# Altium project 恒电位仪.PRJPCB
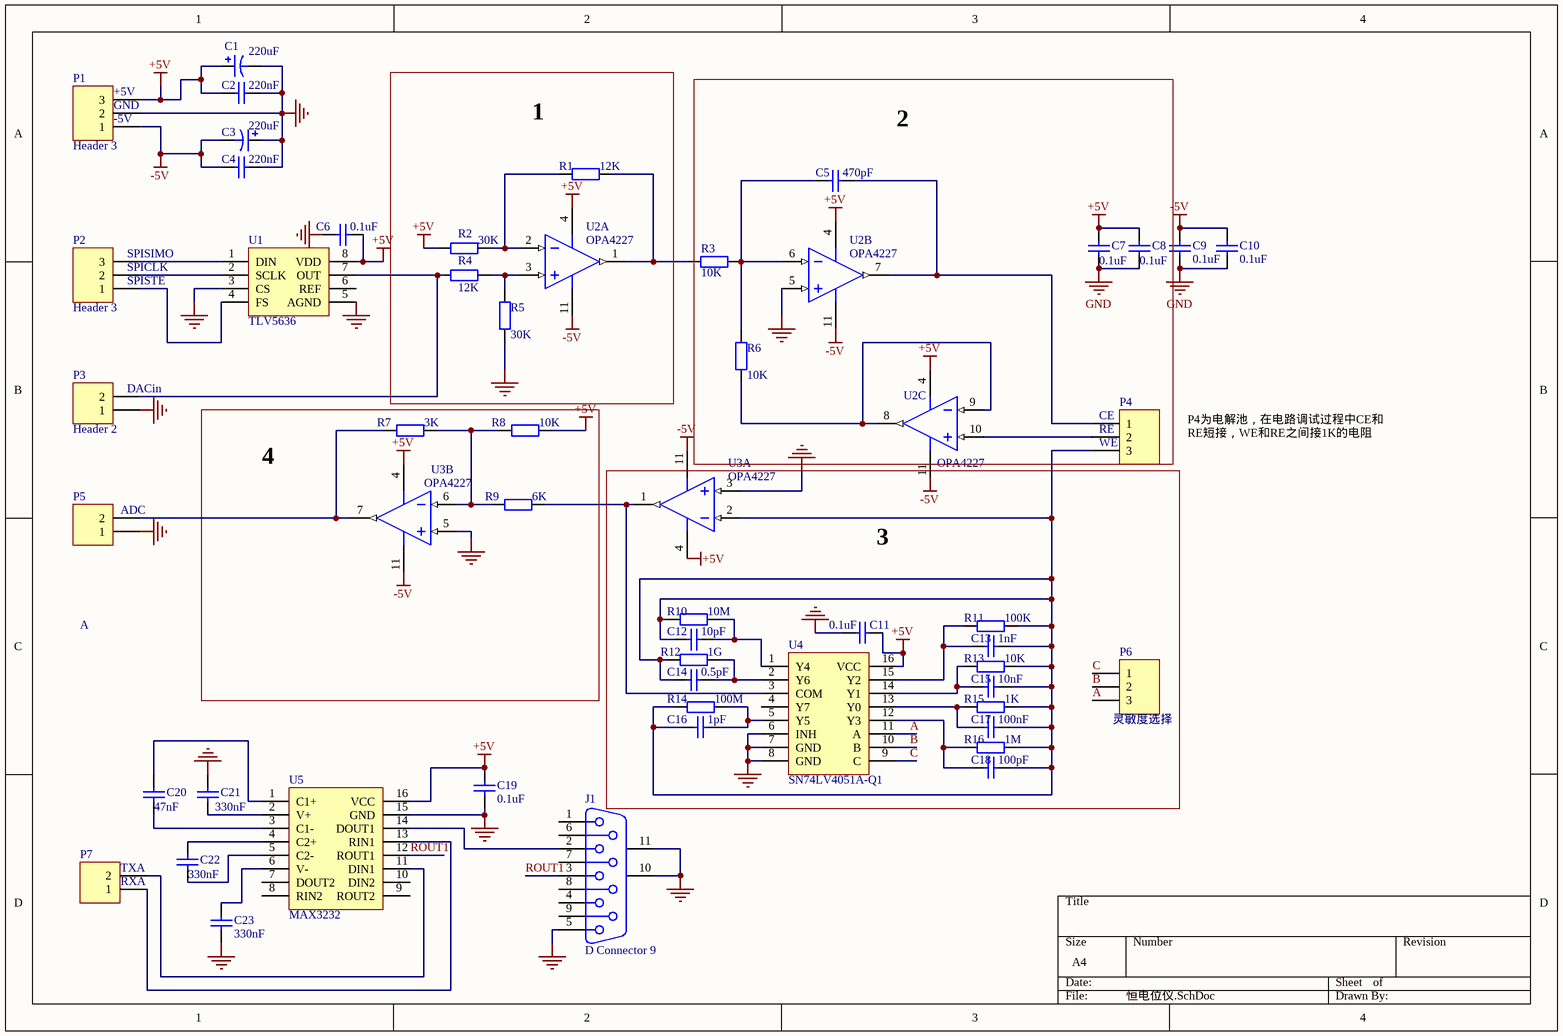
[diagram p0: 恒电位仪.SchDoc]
1 sheet, 52 parts. Net scope: global (net labels, ports and power ports of the same name join across sheets).
Board file: 恒电位仪.PcbDoc

## Sheet 恒电位仪.SchDoc
size A4

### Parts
C1  value 220uF  [R38]  (hidden comment: Cap Pol1)
C2  value 220nF  [CAPR5-4X5]  (hidden comment: Cap)
C3  value 220uF  [R38]  (hidden comment: Cap Pol1)
C4  value 220nF  [CAPR5-4X5]  (hidden comment: Cap)
C5  value 470pF  [C0805]  (hidden comment: Cap)
C6  value 0.1uF  [C0805]  (hidden comment: Cap)
C7  value 0.1uF  [C0805]  (hidden comment: Cap)
C8  value 0.1uF  [C0805]  (hidden comment: Cap)
C9  value 0.1uF  [C0805]  (hidden comment: Cap)
C10  value 0.1uF  [C0805]  (hidden comment: Cap)
C11  value 0.1uF  [C0805]  (hidden comment: Cap)
C12  value 10pF  [C0805]  (hidden comment: Cap)
C13  value 1nF  [C0805]  (hidden comment: Cap)
C14  value 0.5pF  [C0805]  (hidden comment: Cap)
C15  value 10nF  [C0805]  (hidden comment: Cap)
C16  value 1pF  [C0805]  (hidden comment: Cap)
C17  value 100nF  [C0805]  (hidden comment: Cap)
C18  value 100pF  [C0805]  (hidden comment: Cap)
C19  value 0.1uF  [C0805]  (hidden comment: Cap)
C20  value 47nF  [C0805]  (hidden comment: Cap)
C21  value 330nF  [C0805]  (hidden comment: Cap)
C22  value 330nF  [C0805]  (hidden comment: Cap)
C23  value 330nF  [C0805]  (hidden comment: Cap)
J1  D Connector 9  [DSUB1.385-2H9]
P1  Header 3  [HDR1X3]
P2  Header 3  [HDR1X3]
P3  Header 2  [HDR1X2]
P4  Header 3  [HDR1X3]  (value not drawn)
P5  Header 2  [HDR1X2]  (value not drawn)
P6  Header 3  [HDR1X3]  (value not drawn)
P7  Header 2  [HDR1X2]  (value not drawn)
R1  value 12K  [6-0805]  (hidden comment: Res2)
R2  value 30K  [6-0805]  (hidden comment: Res2)
R3  value 10K  [6-0805]  (hidden comment: Res2)
R4  value 12K  [6-0805]  (hidden comment: Res2)
R5  value 30K  [6-0805]  (hidden comment: Res2)
R6  value 10K  [6-0805]  (hidden comment: Res2)
R7  value 3K  [6-0805]  (hidden comment: Res2)
R8  value 10K  [6-0805]  (hidden comment: Res2)
R9  value 6K  [6-0805]  (hidden comment: Res2)
R10  value 10M  [AXIAL-0.4]  (hidden comment: Res2)
R11  value 100K  [AXIAL-0.4]  (hidden comment: Res2)
R12  value 1G  [AXIAL-0.4]  (hidden comment: Res2)
R13  value 10K  [AXIAL-0.4]  (hidden comment: Res2)
R14  value 100M  [AXIAL-0.4]  (hidden comment: Res2)
R15  value 1K  [AXIAL-0.4]  (hidden comment: Res2)
R16  value 1M  [AXIAL-0.4]  (hidden comment: Res2)
U1  TLV5636  [TLV5636]
U2  OPA4227  [OPA4227]  (parts A,B,C of 4)
U3  OPA4227  [OPA4227]  (parts A,B of 4)
U4  SN74LV4051A-Q1  [SN74LV4051A-Q1]
U5  MAX3232  [MAX3232]

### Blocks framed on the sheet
1: R1 R2 R4 R5 U2
2: C5 C7 C8 P4 R3 R6 U2
4: R7-R9 U3
3: C11-C18 P6 R10-R16 U3 U4

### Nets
+5V: C1.1 C2.1 C6.1 C7.1 C8.1 C11.2 C19.1 P1.3 R2.1 R8.1 U1.8(VDD) U2.4(V+) U3.4(V+) U4.16(VCC) U5.16(VCC)
-5V: C3.2 C4.1 C9.1 C10.1 P1.1 U2.11(V-) U3.11(V-)
GND: C1.2 C2.2 C3.1 C4.2 C6.2 C7.2 C8.2 C9.2 C10.2 C11.1 C19.2 C21.1 C23.2 J1.5 J1.10(MH1) J1.11(MH2) P1.2 P3.1 P5.1 R5.1 U1.3(CS) U1.5(AGND) U2.5(IN+) U3.3(IN+) U3.5(IN+) U4.6(INH) U4.7(GND) U4.8(GND) U5.15(GND)
A: P6.3 U4.11(A)
B: P6.2 U4.10(B)
C: P6.1 U4.9(C)
ROUT1: J1.3 U5.12(ROUT1)
NetC5_1: C5.1 P4.1 U2.7(OUT)
NetC5_2: C5.2 R3.1 R6.2 U2.6(IN-)
NetC12_1: C12.1 R10.1 U4.1(Y4)
NetC12_2: C12.2 C13.1 C14.2 C15.1 C16.2 C17.1 C18.1 P4.3 R10.2 R11.1 R12.2 R13.1 R14.2 R15.1 R16.1 U3.2(IN-)
NetC13_2: C13.2 R11.2 U4.15(Y2)
NetC14_1: C14.1 R12.1 U4.2(Y6)
NetC15_2: C15.2 R13.2 U4.14(Y1)
NetC16_1: C16.1 R14.1 U4.5(Y5)
NetC17_2: C17.2 R15.2 U4.13(Y0)
NetC18_2: C18.2 R16.2 U4.12(Y3)
NetC20_1: C20.1 U5.1(C1+)
NetC20_2: C20.2 U5.3(C1-)
NetC21_2: C21.2 U5.2(V+)
NetC22_1: C22.1 U5.4(C2+)
NetC22_2: C22.2 U5.5(C2-)
NetC23_1: C23.1 U5.6(V-)
NetJ1_2: J1.2 U5.14(DOUT1)
NetP2_1: P2.1 U1.4(FS)
NetP2_2: P2.2 U1.2(SCLK)
NetP2_3: P2.3 U1.1(DIN)
NetP3_2: P3.2 R4.1 U1.7(OUT)
NetP4_2: P4.2 U2.10(IN+)
NetP5_2: P5.2 R7.2 U3.7(OUT)
NetP7_1: P7.1 U5.13(RIN1)
NetP7_2: P7.2 U5.11(DIN1)
NetR1_1: R1.1 R2.2 U2.2(IN-)
NetR1_2: R1.2 R3.2 U2.1(OUT)
NetR4_2: R4.2 R5.2 U2.3(IN+)
NetR6_1: R6.1 U2.8(OUT) U2.9(IN-)
NetR7_1: R7.1 R8.2 R9.2 U3.6(IN-)
NetR9_1: R9.1 U3.1(OUT) U4.3(COM)

Not connected (* = marked no-connect by the designer): J1 1 4 6 7 8 9; U1 6(REF); U4 4(Y7); U5 7(DOUT2) 8(RIN2) 9(ROUT2) 10(DIN2)

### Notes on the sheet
- (near P1) +5V
- (near P1) GND
- (near P1) -5V
- (near P2) SPISIMO
- (near P2) SPICLK
- (near P2) SPISTE
- (near P3) DACin
- (near P4) CE
- (near P4) RE
- (near P4) WE
- (near P5) ADC
- P4为电解池，在电路调试过程中CE和RE短接，WE和RE之间接1K的电阻
- A
- (near P6) 灵敏度选择
- (near P7) TXA
- (near P7) RXA

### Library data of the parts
C1 C3 = Cap Pol1: Polarized Capacitor (Radial)
C2 C4-C23 = Cap: Capacitor
J1 = D Connector 9: Receptacle Assembly, 9 Position, Right Angle; PackageDocument: O; Positions: 9
P1 P2 P4 P6 = Header 3: Header, 3-Pin
P3 P5 P7 = Header 2: Header, 2-Pin
R1-R16 = Res2: Resistor
U2 U3 = OPA4227: ComponentAvailability: Obsolete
